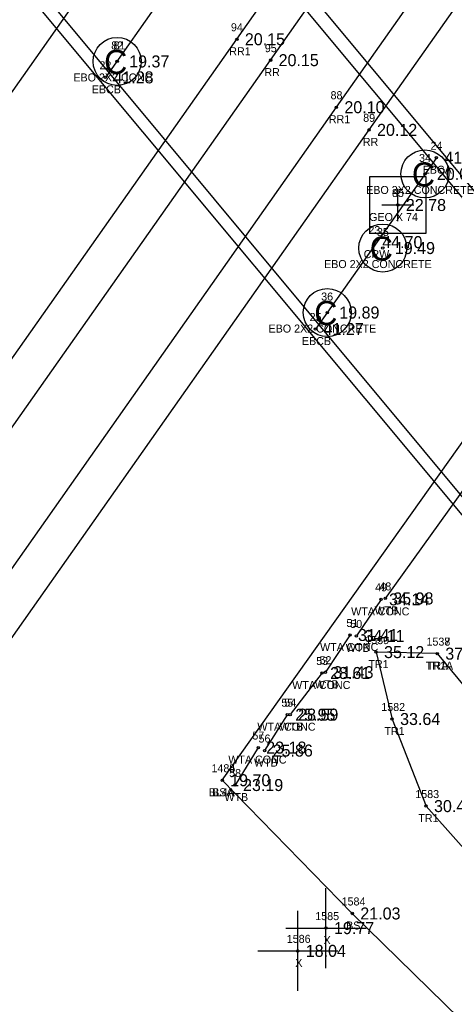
# Model space of a CAD drawing. Extents: x 2042211 to 2045853, y 303080 to 309569.
# Drawn here: x 2043458.3 to 2043512.6, y 305766.6 to 305889.6 of the extents above; entities that cross this region are included whole.
import ezdxf

# ---------------------------------------------------------------- set-up
doc = ezdxf.new("R2010")
doc.units = 0
for name, color, linetype in [('BR_500YR_SCOUR', 7, 'Continuous'), ('RD_DTM_BkLn1', 7, 'Continuous'), ('RD_DTM_BkLn2', 7, 'Continuous'), ('RD_DTM_BkLn_txCode', 7, 'Continuous'), ('RD_EX_Bridge_txCode', 7, 'Continuous'), ('RD_EX_Misc', 7, 'Continuous'), ('RD_EX_Misc_txCode', 7, 'Continuous'), ('RD_EX_RailRoad', 7, 'Continuous'), ('RD_EX_RailRoad_txCode', 7, 'Continuous'), ('RD_EX_TX_Bridge_ELEV', 7, 'Continuous'), ('RD_EX_TX_Misc_ELEV', 7, 'Continuous'), ('RD_EX_TX_RailRoad_ELEV', 7, 'Continuous'), ('RD_EX_TX_VEG_ELEV', 7, 'Continuous'), ('RD_EX_VEG_txCode', 7, 'Continuous'), ('RD_HC_Survey_ELEV', 7, 'Continuous'), ('RD_HC_Survey_txCode', 7, 'Continuous'), ('RD_SMD_Locator', 7, 'Continuous')]:
    doc.layers.add(name, color=color, linetype=linetype)

msp = doc.modelspace()

# ---------------------------------------------------------------- linework, layer by layer
at = {"layer": 'BR_500YR_SCOUR'}
for p, q in [((2043443.49, 305911.86), (2043519.61, 305820.49)), ((2043484.12, 305903.82), (2043469.04, 305882.43)), ((2043510.41, 305872.39), (2043495.3, 305850.98)), ((2043505.59, 305864.48), (2043505.59, 305868.48)), ((2043507.59, 305866.48), (2043503.59, 305866.48))]:
    msp.add_line(p, q, dxfattribs=at)
for points in [[(2043462.27, 305936.28), (2043464.78, 305928.69), (2043533.86, 305845.73), (2043538.2, 305846.31)], [(2043457.57, 305934.73), (2043443.33, 305914.37), (2043521.86, 305820.1), (2043536.15, 305840.42), (2043457.57, 305934.73)], [(2043510.52, 305810.42), (2043502.87, 305810.61), (2043504.87, 305802.25), (2043509.11, 305791.37), (2043594.27, 305695.69), (2043658.16, 305620.89), (2043717.86, 305542.89), (2043784.35, 305466.31), (2043848.97, 305392.37), (2043916.01, 305316.79), (2043971.98, 305240.84)], [(2043510.52, 305810.42), (2043528.58, 305788.55), (2043603.52, 305706.8), (2043669.11, 305631.48), (2043746.08, 305529.27), (2043781.83, 305496.01), (2043793.11, 305482.33), (2043857.16, 305399.04), (2043922.61, 305323.93), (2043978.69, 305250.66), (2043978.39, 305246.16), (2043971.98, 305240.84)]]:
    msp.add_lwpolyline(points, dxfattribs=at)
msp.add_lwpolyline([(2043509.12, 305870.02), (2043502.05, 305870.02), (2043502.05, 305862.95), (2043509.12, 305862.95)], close=True, dxfattribs=at)
for centre, radius in [((2043470.51, 305884.42), 3), ((2043470.51, 305884.42), 3), ((2043470.51, 305884.42), 0.15), ((2043470.51, 305884.42), 0.15), ((2043469.04, 305882.43), 0.15), ((2043508.97, 305870.36), 3), ((2043510.41, 305872.39), 0.15), ((2043508.97, 305870.36), 0.15), ((2043505.59, 305866.48), 0.15), ((2043503.71, 305861.1), 3), ((2043503.71, 305861.1), 0.15), ((2043496.77, 305853.04), 3), ((2043496.77, 305853.04), 0.15), ((2043495.3, 305850.98), 0.15), ((2043502.87, 305810.61), 0.15), ((2043510.52, 305810.42), 0.15), ((2043510.52, 305810.42), 0.15), ((2043504.87, 305802.25), 0.15), ((2043509.11, 305791.37), 0.15)]:
    msp.add_circle(centre, radius, dxfattribs=at)
at = {"layer": 'RD_DTM_BkLn1'}
msp.add_line((2043483.64, 305794.6), (2043547.74, 305884.86), dxfattribs=at)
at = {"layer": 'RD_DTM_BkLn2'}
for p, q in [((2043532.51, 305857.06), (2043504.02, 305817.32)), ((2043503.49, 305817.2), (2043500.41, 305812.63)), ((2043499.61, 305812.75), (2043496.53, 305808.1)), ((2043496.12, 305808), (2043492.13, 305802.8)), ((2043491.77, 305802.79), (2043488.94, 305798.31)), ((2043488.14, 305798.68), (2043485.24, 305794))]:
    msp.add_line(p, q, dxfattribs=at)
msp.add_lwpolyline([(2043483.64, 305794.6), (2043499.9, 305777.95), (2043515.27, 305762.9), (2043518.21, 305761.16), (2043589.07, 305691.11), (2043649.23, 305614.13), (2043716.37, 305541.69), (2043781.37, 305463.81), (2043848.97, 305392.37), (2043918.9, 305320.25), (2043979.36, 305247.54), (2043984.14, 305244.91)], dxfattribs=at)
at = {"layer": 'RD_EX_Misc'}
for p, q in [((2043496.61, 305771.12), (2043496.61, 305781.12)), ((2043493.08, 305768.28), (2043493.08, 305778.28)), ((2043491.61, 305776.12), (2043501.61, 305776.12)), ((2043488.08, 305773.28), (2043498.08, 305773.28))]:
    msp.add_line(p, q, dxfattribs=at)
at = {"layer": 'RD_EX_RailRoad'}
for points in [[(2043321.05, 305686.98), (2043469.61, 305897.99), (2043578.86, 306053.03)], [(2043362.26, 305712.2), (2043485.47, 305887.19), (2043594.33, 306041.82)], [(2043366.36, 305709.46), (2043489.69, 305884.58), (2043598.29, 306038.89)], [(2043374.76, 305703.68), (2043497.91, 305878.7), (2043606.68, 306033.02)], [(2043378.92, 305700.92), (2043501.99, 305875.87), (2043610.75, 306030.1)]]:
    msp.add_lwpolyline(points, dxfattribs=at)
at = {"layer": 'RD_SMD_Locator'}
for centre in [(2043485.47, 305887.19), (2043489.69, 305884.58), (2043497.91, 305878.7), (2043501.99, 305875.87), (2043503.49, 305817.2), (2043504.02, 305817.32), (2043499.61, 305812.75), (2043500.41, 305812.63), (2043496.12, 305808), (2043496.53, 305808.1), (2043491.77, 305802.79), (2043492.13, 305802.8), (2043488.14, 305798.68), (2043488.94, 305798.31), (2043483.64, 305794.6), (2043483.64, 305794.6), (2043485.24, 305794), (2043499.9, 305777.95), (2043496.61, 305776.12), (2043493.08, 305773.28)]:
    msp.add_circle(centre, 0.15, dxfattribs=at)

# ---------------------------------------------------------------- texts
at = {"layer": 'BR_500YR_SCOUR'}
for s, height, p in [('C', 3, (2043468.88, 305882.86)), ('C', 3, (2043468.88, 305882.86)), ('C', 3, (2043507.34, 305868.8)), ('85', 1, (2043504.86, 305867.48)), ('GEO X 74', 1, (2043502, 305864.48)), ('C', 3, (2043502.08, 305859.54)), ('C', 3, (2043495.14, 305851.48))]:
    msp.add_text(s, height=height, dxfattribs=at).set_placement(p)
at = {"layer": 'RD_DTM_BkLn_txCode'}
for s, p in [('1484', (2043482.3, 305795.6)), ('1485', (2043482.3, 305795.6)), ('BL4A', (2043481.95, 305792.6)), ('BSA', (2043482.38, 305792.6)), ('1584', (2043498.56, 305778.95)), ('BS', (2043499.12, 305775.95))]:
    msp.add_text(s, height=1, dxfattribs=at).set_placement(p)
at = {"layer": 'RD_EX_Bridge_txCode'}
for s, p in [('82', (2043469.77, 305885.92)), ('81', (2043470.06, 305885.92)), ('22', (2043468.3, 305883.43)), ('EBO 2X2 CONC', (2043465.04, 305881.92)), ('EBO 2X2 CONC', (2043465.04, 305881.92)), ('EBCB', (2043467.34, 305880.43)), ('24', (2043509.68, 305873.39)), ('34', (2043508.24, 305871.86)), ('EBCA', (2043508.69, 305870.39)), ('EBO 2X2 CONCRETE', (2043501.63, 305867.86)), ('35', (2043502.98, 305862.6)), ('EBO 2X2 CONCRETE', (2043496.37, 305858.6)), ('36', (2043496.01, 305854.54)), ('25', (2043494.56, 305851.98)), ('EBO 2X2 CONCRETE', (2043489.43, 305850.54)), ('EBCB', (2043493.6, 305848.98))]:
    msp.add_text(s, height=1, dxfattribs=at).set_placement(p)
at = {"layer": 'RD_EX_Misc_txCode'}
for s, p in [('49', (2043502.75, 305818.2)), ('48', (2043503.28, 305818.32)), ('WTA CONC', (2043499.75, 305815.2)), ('WTB', (2043502.69, 305815.32)), ('51', (2043499.16, 305813.75)), ('50', (2043499.64, 305813.63)), ('WTA CONC', (2043495.87, 305810.75)), ('WTB', (2043499.08, 305810.63)), ('53', (2043495.39, 305809)), ('52', (2043495.8, 305809.1)), ('WTA CONC', (2043492.38, 305806)), ('WTB', (2043495.2, 305806.1)), ('55', (2043491.03, 305803.79)), ('54', (2043491.4, 305803.8)), ('57', (2043487.41, 305799.68)), ('WTA CONC', (2043488.03, 305800.79)), ('WTB', (2043490.8, 305800.8)), ('56', (2043488.18, 305799.31)), ('WTA CONC', (2043484.4, 305796.68)), ('WTB', (2043487.61, 305796.31)), ('58', (2043484.51, 305795)), ('WTB', (2043483.91, 305792)), ('1585', (2043495.27, 305777.12)), ('1586', (2043491.71, 305774.28)), ('X', (2043496.3, 305774.12)), ('X', (2043492.77, 305771.28))]:
    msp.add_text(s, height=1, dxfattribs=at).set_placement(p)
at = {"layer": 'RD_EX_RailRoad_txCode'}
for s, p in [('94', (2043484.73, 305888.19)), ('RR1', (2043484.52, 305885.19)), ('95', (2043488.96, 305885.58)), ('RR', (2043488.91, 305882.58)), ('88', (2043497.18, 305879.7)), ('RR1', (2043496.97, 305876.7)), ('89', (2043501.26, 305876.87)), ('RR', (2043501.21, 305873.87))]:
    msp.add_text(s, height=1, dxfattribs=at).set_placement(p)
at = {"layer": 'RD_EX_TX_Bridge_ELEV'}
for s, p in [('19.37', (2043472.01, 305883.67)), ('19.37', (2043472.01, 305883.67)), ('41.28', (2043470.04, 305881.68)), ('41.29', (2043511.41, 305871.64)), ('20.08', (2043510.47, 305869.61)), ('19.49', (2043505.21, 305860.35)), ('19.89', (2043498.27, 305852.29)), ('41.27', (2043496.3, 305850.23))]:
    msp.add_text(s, height=1.5, dxfattribs=at).set_placement(p)
at = {"layer": 'RD_EX_TX_Misc_ELEV'}
for s, p in [('34.14', (2043504.49, 305816.45)), ('35.98', (2043505.02, 305816.57)), ('31.41', (2043500.61, 305812)), ('34.11', (2043501.41, 305811.88)), ('28.61', (2043497.12, 305807.25)), ('31.43', (2043497.53, 305807.35)), ('25.95', (2043492.77, 305802.04)), ('28.59', (2043493.13, 305802.05)), ('23.18', (2043489.14, 305797.93)), ('25.86', (2043489.94, 305797.56)), ('19.70', (2043484.64, 305793.85)), ('19.70', (2043484.64, 305793.85)), ('23.19', (2043486.24, 305793.25)), ('21.03', (2043500.9, 305777.2)), ('19.77', (2043497.61, 305775.37)), ('18.04', (2043494.08, 305772.53))]:
    msp.add_text(s, height=1.5, dxfattribs=at).set_placement(p)
at = {"layer": 'RD_EX_TX_RailRoad_ELEV'}
for s, p in [('20.15', (2043486.47, 305886.44)), ('20.15', (2043490.69, 305883.83)), ('20.10', (2043498.91, 305877.95)), ('20.12', (2043502.99, 305875.12))]:
    msp.add_text(s, height=1.5, dxfattribs=at).set_placement(p)
at = {"layer": 'RD_EX_TX_VEG_ELEV'}
for s, p in [('35.12', (2043503.87, 305809.86)), ('37.94', (2043511.52, 305809.67)), ('37.94', (2043511.52, 305809.67)), ('33.64', (2043505.87, 305801.5)), ('30.47', (2043510.11, 305790.62))]:
    msp.add_text(s, height=1.5, dxfattribs=at).set_placement(p)
at = {"layer": 'RD_EX_VEG_txCode'}
for s, p in [('1539', (2043501.52, 305811.61)), ('1537', (2043509.17, 305811.42)), ('1538', (2043509.17, 305811.42)), ('TR1', (2043501.91, 305808.61)), ('TR1A', (2043509.07, 305808.42)), ('TRA', (2043509.23, 305808.42)), ('1582', (2043503.52, 305803.25)), ('TR1', (2043503.91, 305800.25)), ('1583', (2043507.77, 305792.37)), ('TR1', (2043508.15, 305789.37))]:
    msp.add_text(s, height=1, dxfattribs=at).set_placement(p)
at = {"layer": 'RD_HC_Survey_ELEV'}
for s, p in [('22.78', (2043506.59, 305865.73)), ('44.70', (2043503.64, 305861.09))]:
    msp.add_text(s, height=1.5, dxfattribs=at).set_placement(p)
at = {"layer": 'RD_HC_Survey_txCode'}
for s, p in [('23', (2043501.91, 305862.84)), ('CRW', (2043501.32, 305859.84))]:
    msp.add_text(s, height=1, dxfattribs=at).set_placement(p)

doc.saveas('drawing.dxf')
